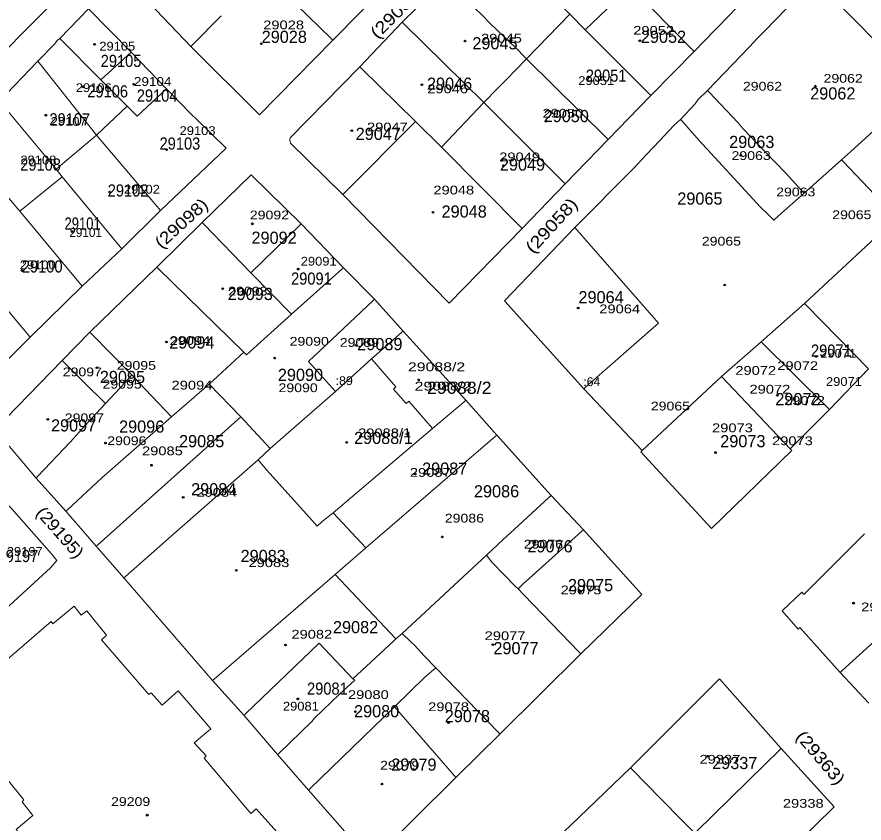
# Model space of a CAD drawing. Extents: x 650553 to 652508, y 239277 to 241647.
# Drawn here: x 650778.4 to 651029.3, y 239869.5 to 240108.2 of the extents above; entities that cross this region are included whole.
import ezdxf

# ---------------------------------------------------------------- set-up
doc = ezdxf.new("R2010")
doc.units = 0
doc.header["$PDMODE"] = 32
doc.header["$PDSIZE"] = 0.5
for name, color, linetype in [('19', 7, 'Continuous'), ('20', 7, 'Continuous'), ('6', 7, 'Continuous')]:
    doc.layers.add(name, color=color, linetype=linetype)
doc.layers.add('3', color=7, linetype='Continuous', lineweight=13)
doc.layers.add('5', color=7, linetype='Continuous', lineweight=13)

msp = doc.modelspace()

# ---------------------------------------------------------------- linework, layer by layer
at = {"layer": '3'}
for p, q in [((651000, 240104.22), (651014.69, 240119.32)), ((650986.44, 239912.2), (651004.77, 239891.58))]:
    msp.add_line(p, q, dxfattribs=at)
for points in [[(650975.44, 240248.44), (650994.17, 240226.84), (650977.88, 240210.19), (650963.32, 240195.05), (650948.63, 240180.21), (650934.05, 240165.2), (650919.2, 240150.25), (650903.76, 240134.01), (650887.65, 240117.31), (650871.97, 240101.3)], [(650930.92, 240145.99), (650924.769, 240139.63), (650918.26, 240132.9), (650905.2, 240119.22), (650892.49, 240106.64), (650880, 240093.44)], [(650766.31, 240143.8), (650775.98, 240134.27), (650792.47, 240117.44), (650792.29, 240115.83), (650763.49, 240086.71), (650744.41, 240067.5), (650736.33, 240059.47), (650735.05, 240058.07), (650734.43, 240057.51), (650722.23, 240045.33)], [(650871.97, 240101.3), (650850.3, 240079.24), (650829.93, 240099.47), (650819.64, 240110.18), (650810.53, 240119.41)], [(650773.2, 240083.22), (650784.6, 240095.08), (650789.44, 240100.03), (650790.43, 240101.3), (650791.13, 240101.84), (650799.66, 240110.57), (650812.24, 240097.72), (650822.72, 240086.91), (650830, 240079.39), (650831.7, 240077.84), (650840.34, 240069.3), (650820.91, 240050.84), (650809.49, 240039.55), (650797.79, 240028.48), (650782.37, 240013.42), (650768.89, 240000)], [(650978.95, 240097.99), (650985.03, 240104.18), (650986.07, 240105.29), (650991.82, 240111.21)], [(651000, 240104.22), (650997.68, 240101.84), (650995.41, 240099.33), (650982.94, 240086.4)], [(650953.53, 240071.89), (650962.616, 240081.263), (650966.16, 240084.92), (650978.95, 240097.99)], [(650880, 240093.44), (650859.32, 240072.42), (650859.21, 240071.78), (650859.48, 240070.81), (650874.97, 240055.59)], [(650982.94, 240086.4), (650980.21, 240083.73), (650979.27, 240082.47), (650974.97, 240077.81)], [(650974.97, 240077.81), (650974.27, 240077.27), (650972.98, 240076), (650968.861, 240071.631), (650964.91, 240067.44), (650960.97, 240063.32), (650943.69, 240045.86)], [(650928.01, 240045.51), (650940.8, 240058.76), (650953.53, 240071.89)], [(650833.3, 240047.34), (650847.81, 240061.43), (650862.6, 240046.9), (650875.1, 240033.95), (650884.29, 240024.61), (650892.8, 240015.16), (650911.36, 239994.7), (650920.54, 239984.38), (650936.59, 239966.5), (650946.16, 239956.31), (650963.51, 239937.15)], [(650874.97, 240055.59), (650906.41, 240023.45), (650928.01, 240045.51)], [(650771.89, 239986.02), (650791.8, 240006.47), (650800.06, 240014.9), (650819.81, 240034.14), (650833.3, 240047.34)], [(650943.69, 240045.86), (650922.798, 240024.153), (650946.26, 239998.12), (650963.63, 239979.83)], [(650963.63, 239979.83), (650963.19, 239979.42), (650984.08, 239956.68), (651007.923, 239979.861), (651007.45, 239980.27), (651019.018, 239991.973), (651030.64, 240004.03)], [(650908.41, 239883.02), (650883.34, 239858.18), (650864.77, 239879.28), (650855.55, 239889.77), (650845.58, 239901.42), (650836.36, 239911.69), (650810.07, 239942.07), (650801.92, 239951.45), (650792.87, 239961.83), (650784.09, 239971.6), (650771.89, 239986.02)], [(650775.13, 239932.91), (650788.329, 239945.049), (650790.275, 239947.215), (650788.627, 239949.191), (650776.82, 239962.65), (650762.84, 239977.13)], [(651029.394, 239955.14), (651011.428, 239937.153), (651010.901, 239937.895), (651005.075, 239932.349), (651009.776, 239926.918), (651010.311, 239927.45), (651022.23, 239914.101), (651030.731, 239905.003)], [(650963.51, 239937.15), (650945.45, 239919.6), (650921.48, 239895.81), (650908.41, 239883.02)], [(650758.53, 239902.67), (650765.192, 239907.872), (650764.516, 239908.49), (650788.613, 239929.179), (650789.086, 239928.488), (650795.35, 239933.7), (650797.42, 239931.11), (650799.14, 239932.39), (650804.99, 239925.16), (650803.46, 239923.73), (650817.53, 239907.6), (650818.21, 239908.05), (650821.441, 239904.446), (650826.146, 239908.699), (650835.897, 239897.399), (650830.96, 239893.24), (650834.46, 239889.42), (650833.85, 239888.76), (650847.66, 239872.31), (650849.29, 239873.74), (650855.37, 239866.92), (650854.34, 239866.07), (650856.61, 239863.11), (650871.916, 239846.694)], [(650926.38, 239808.25), (650907.36, 239830.06), (650907.67, 239834.39), (650925.58, 239852.98), (650942.36, 239868.78), (650960.13, 239885.88), (650986.44, 239912.2)], [(650758.53, 239902.67), (650760.73, 239900.19), (650759.19, 239898.72), (650765.32, 239891.73), (650766.99, 239892.99), (650780.49, 239876.39), (650779.94, 239875.79), (650783.12, 239871.78), (650778.188, 239867.604), (650787.995, 239856.292), (650792.37, 239860.72), (650795.54, 239856.63), (650796.29, 239857.11), (650810.17, 239840.72), (650808.48, 239839.35), (650814.17, 239832.2), (650815.19, 239833.07), (650817.72, 239830.34), (650834.635, 239810.007), (650871.916, 239846.694)], [(651004.77, 239891.58), (651020.46, 239874.33), (651009.06, 239863.21), (651008.47, 239863.96), (650986.02, 239841.96), (650973.43, 239829.74), (650960.91, 239817.58), (650937.89, 239794.94), (650926.38, 239808.25)]]:
    msp.add_lwpolyline(points, dxfattribs=at)
at = {"layer": '5'}
for p, q in [((650929.29, 240095.81), (650942.18, 240109.01)), ((650803.28, 240089.58), (650812.24, 240097.72)), ((650779.32, 240050.7), (650791.83, 240060.84)), ((650943.69, 240045.86), (650968.38, 240017.56)), ((650998.84, 240012), (650987.12, 240001.73)), ((650864.75, 240006.2), (650872.74, 239997.26)), ((650798.34, 240000), (650804.67, 239993.75)), ((650812.46, 240002.19), (650810.44, 240000)), ((650814.53, 240000), (650824.2, 239989.77)), ((650987.12, 240001.73), (650963.63, 239979.83)), ((650987.12, 240001.73), (651007.45, 239980.27)), ((650872.07, 239961.33), (650881.77, 239950.98)), ((650872.65, 239943.08), (650890.65, 239924.09))]:
    msp.add_line(p, q, dxfattribs=at)
for points in [[(650918.26, 240132.9), (650918.76, 240132.401), (650942.18, 240109.01), (650946.68, 240104.38)], [(650854.33, 240118.56), (650871.47, 240101.789), (650871.97, 240101.3)], [(650905.2, 240119.22), (650905.7, 240118.739), (650916.28, 240108.57), (650918.43, 240106.37), (650924.82, 240100.3), (650925.76, 240099.39), (650929.29, 240095.81)], [(651014.69, 240119.32), (651015.181, 240118.82), (651034.33, 240099.34), (651038, 240095.56)], [(650946.68, 240104.38), (650950.89, 240108.34), (650956.05, 240113.4), (650959.96, 240117.36)], [(650959.96, 240117.36), (650978.46, 240098.49), (650978.95, 240097.99)], [(650829.93, 240099.47), (650830.427, 240099.97), (650838.9, 240108.5)], [(650892.49, 240106.64), (650892.99, 240106.148), (650916.68, 240082.82)], [(650946.68, 240104.38), (650965.66, 240085.419), (650966.16, 240084.92)], [(650791.13, 240101.84), (650803.28, 240089.58), (650811.03, 240081.77), (650814, 240078.82), (650822.72, 240086.91)], [(650904.16, 240069.62), (650916.68, 240082.82), (650920.75, 240087.02), (650923.24, 240089.48), (650929.29, 240095.81)], [(650929.29, 240095.81), (650953.03, 240072.383), (650953.53, 240071.89)], [(650784.6, 240095.08), (650801.99, 240073.14), (650820.91, 240050.84)], [(650880, 240093.44), (650880.5, 240092.949), (650896.49, 240077.25), (650904.16, 240069.62), (650928.01, 240045.51)], [(650982.94, 240086.4), (650983.414, 240085.9), (650992.02, 240076.82), (650993.53, 240075.08), (651000, 240068.28)], [(651022.59, 240065.87), (651025.24, 240068.24), (651034.21, 240076.35), (651037.83, 240079.55), (651046.01, 240087.16)], [(650773.2, 240083.22), (650790.02, 240063.09), (650791.83, 240060.84), (650809.49, 240039.55)], [(650916.68, 240082.82), (650940.3, 240059.259), (650940.8, 240058.76)], [(650790.02, 240063.09), (650801.99, 240073.14), (650811.03, 240081.77)], [(650974.97, 240077.81), (650975.415, 240077.31), (650981.3, 240070.69), (650982.86, 240069.06), (650998.65, 240051.9)], [(650874.97, 240055.59), (650875.467, 240056.09), (650896.49, 240077.25)], [(650761.69, 240071.64), (650777.54, 240052.71), (650779.32, 240050.7), (650797.79, 240028.48)], [(651000, 240068.28), (651006.11, 240061.9), (651011.052, 240056.51), (651011.51, 240056.01)], [(650999.859, 240050.655), (651000.5, 240050.041), (651002.6, 240048.03), (651003.92, 240049.33), (651011.51, 240056.01), (651022.59, 240065.87)], [(651022.59, 240065.87), (651023.066, 240065.37), (651038.214, 240049.46), (651038.69, 240048.96)], [(650998.84, 240012), (651011.61, 240023.38), (651031.17, 240041.53), (651038.69, 240048.96), (651043.31, 240052.81), (651055.09, 240063.85)], [(650750.35, 240060.27), (650766.03, 240041.88), (650761.91, 240037.76), (650782.37, 240013.42)], [(650998.65, 240051.9), (650999.514, 240051.01), (650999.859, 240050.655)], [(650833.3, 240047.34), (650833.784, 240046.84), (650847.72, 240032.43), (650859.71, 240020.15)], [(650847.72, 240032.43), (650862.1, 240046.414), (650862.6, 240046.9)], [(650819.81, 240034.14), (650820.31, 240033.651), (650845.59, 240008.91)], [(650875.1, 240033.95), (650874.6, 240033.502), (650859.71, 240020.15), (650846.38, 240008.1), (650845.59, 240008.91), (650835.4, 239999.46)], [(650884.29, 240024.61), (650883.79, 240024.139), (650864.75, 240006.2)], [(651011.61, 240023.38), (651012.102, 240022.88), (651030.64, 240004.03)], [(650968.38, 240017.56), (650946.76, 239998.559), (650946.26, 239998.12)], [(650800.06, 240014.9), (650800.548, 240014.4), (650812.46, 240002.19), (650814.53, 240000)], [(650892.8, 240015.16), (650892.3, 240014.723), (650883.43, 240006.97), (650872.74, 239997.26)], [(650998.84, 240012), (651018.518, 239992.469), (651019.018, 239991.973)], [(650791.8, 240006.47), (650792.3, 240005.975), (650798.34, 240000)], [(650883.43, 240006.97), (650890.671, 239998.708), (650889.908, 239997.999), (650893.73, 239993.745), (650894.519, 239994.454), (650901.48, 239986.3)], [(650810.44, 240000), (650804.67, 239993.75), (650800.53, 239989.25), (650794.31, 239982.43)], [(650835.4, 239999.46), (650824.2, 239989.77), (650803.59, 239971.68)], [(650835.4, 239999.46), (650844.71, 239989.81), (650853.45, 239980.41)], [(650872.74, 239997.26), (650853.45, 239980.41), (650849.87, 239977.03), (650826.58, 239956.58), (650822.45, 239953)], [(650911.36, 239994.7), (650910.86, 239994.275), (650901.48, 239986.3), (650872.07, 239961.33), (650868.82, 239958.76), (650867.29, 239957.46), (650865.02, 239960), (650853.32, 239973.05), (650852.44, 239974), (650849.87, 239977.03)], [(650844.71, 239989.81), (650802.42, 239951.898), (650801.92, 239951.45)], [(650794.31, 239982.43), (650784.562, 239972.1), (650784.09, 239971.6)], [(650920.54, 239984.38), (650920.04, 239983.949), (650881.77, 239950.98), (650872.65, 239943.08)], [(650803.59, 239971.68), (650793.37, 239962.289), (650792.87, 239961.83)], [(650936.59, 239966.5), (650936.09, 239966.04), (650926.92, 239957.6), (650922.32, 239953.37), (650917.47, 239948.86), (650892.47, 239925.68), (650890.65, 239924.09), (650889.94, 239923.37), (650877.89, 239912.21), (650867.89, 239922.79)], [(650946.16, 239956.31), (650945.66, 239955.862), (650928.27, 239940.29), (650926.85, 239938.86)], [(650822.45, 239953), (650810.57, 239942.511), (650810.07, 239942.07)], [(650917.47, 239948.86), (650919.1, 239946.75), (650926.16, 239939.49), (650926.85, 239938.86), (650928.52, 239937.04)], [(650872.65, 239943.08), (650836.86, 239912.122), (650836.36, 239911.69)], [(650928.52, 239937.04), (650944.965, 239920.1), (650945.45, 239919.6)], [(651022.23, 239914.101), (651022.73, 239914.554), (651046.15, 239935.78)], [(650892.47, 239925.68), (650895.08, 239923.13), (650896.15, 239922.14), (650898.98, 239919.06), (650902.44, 239915.48)], [(650867.89, 239922.79), (650846.08, 239901.899), (650845.58, 239901.42)], [(650902.44, 239915.48), (650899.25, 239912.73), (650890.26, 239903.97)], [(650902.44, 239915.48), (650920.996, 239896.31), (650921.48, 239895.81)], [(650877.89, 239912.21), (650878.49, 239911.87), (650873.99, 239907.67), (650866.54, 239900.55), (650865.71, 239899.54)], [(650890.26, 239903.97), (650865.27, 239879.764), (650864.77, 239879.28)], [(650890.26, 239903.97), (650907.977, 239883.52), (650908.41, 239883.02)], [(650865.71, 239899.54), (650856.05, 239890.251), (650855.55, 239889.77)], [(651000, 239886.91), (651004.27, 239891.09), (651004.77, 239891.58)], [(651000, 239886.91), (650979.43, 239866.78), (650979.19, 239866.43), (650977.59, 239864.89), (650976.17, 239863.49), (650970.39, 239857.73), (650961.58, 239849), (650957.95, 239845.67), (650945.33, 239833.29)], [(650960.13, 239885.88), (650960.617, 239885.38), (650968.98, 239876.79), (650975.37, 239870.37), (650978.06, 239867.64), (650979.19, 239866.43)]]:
    msp.add_lwpolyline(points, dxfattribs=at)
at = {"layer": '6'}
for p in [(650801.407, 240100.075), (650850.812, 240100.24), (650911.13, 240101.02), (650962.893, 240101.14), (650947.673, 240090.45), (650797.985, 240087.49), (650812.991, 240088.27), (650898.348, 240088.13), (651014.845, 240087.665), (650786.966, 240079.085), (650935.146, 240077.285), (650877.577, 240074.515), (650822.751, 240068.875), (650992.789, 240067.215), (650922.469, 240064.165), (650805.899, 240056.345), (650901.659, 240050.35), (650848.133, 240046.93), (650794.796, 240044.66), (650779.918, 240033.065), (650861.736, 240033.525), (650839.344, 240027.72), (650988.014, 240028.82), (650944.631, 240021.99), (650822.706, 240011.955), (650878.871, 240010.935), (650854.757, 240007.18), (651015.125, 240007.676), (650802.173, 240004.325), (650897.394, 240000.73), (651003.622, 239996.135), (650787.58, 239989.035), (650876.093, 239982.215), (650804.636, 239982.01), (650985.318, 239979.205), (650818.294, 239975.455), (650896.386, 239972.84), (650827.662, 239965.94), (650904.405, 239954.235), (650931.842, 239952.68), (650843.396, 239944.36), (650945.231, 239937.955), (651026.165, 239934.62), (650857.948, 239922.25), (650919.367, 239922.335), (650861.595, 239906.28), (650878.641, 239902.48), (650906.25, 239899.25), (650983.01, 239889.315), (650886.535, 239881.075), (650817.017, 239871.853)]:
    msp.add_point(p, dxfattribs=at)

# ---------------------------------------------------------------- texts
at = {"layer": '19'}
for s, rotation, width, p in [('(29037)', 44.915, 1.2, (650885.223, 240101.459)), ('(29098)', 42.188, 1.15, (650821.228, 240039.361)), ('(29058)', 47.399, 1.2, (650931.314, 240037.878)), ('(29195)', 311.276, 1.1, (650783.835, 239961.229)), ('(29363)', 310.486, 1.15, (651008.862, 239894.966))]:
    msp.add_text(s, height=3.6, rotation=rotation, dxfattribs=dict(at, width=width)).set_placement(p)
for s, p in [('29028', (650850.909, 240100.506)), ('29052', (650963.201, 240100.506)), ('29045', (650913.293, 240098.59)), ('29046', (650899.858, 240086.619)), ('29062', (651013.339, 240083.744)), ('29050', (650934.408, 240077.041)), ('29047', (650878.743, 240071.774)), ('29063', (650989.346, 240069.378)), ('29049', (650921.452, 240062.676)), ('29065', (650973.99, 240052.618)), ('29048', (650904.176, 240048.789)), ('29092', (650847.888, 240041.017)), ('29093', (650840.825, 240024.366)), ('29064', (650944.716, 240023.407)), ('29094', (650823.548, 240010)), ('29089', (650879.214, 240009.521)), ('29095', (650802.981, 239999.789)), ('29090', (650855.7, 240000.423)), ('29072', (651003.021, 239993.24)), ('29097', (650788.518, 239985.456)), ('29096', (650808.673, 239985.1)), ('29088/1', (650878.254, 239981.747)), ('29085', (650826.429, 239980.79)), ('29073', (650986.705, 239980.789)), ('29087', (650898.411, 239972.649)), ('29084', (650830.017, 239966.546)), ('29086', (650913.767, 239965.945)), ('29076', (650929.601, 239949.664)), ('29083', (650844.664, 239946.79)), ('29075', (650941.598, 239938.171)), ('29082', (650872.017, 239925.721)), ('29077', (650919.524, 239919.495)), ('29080', (650878.254, 239900.82)), ('29078', (650905.128, 239899.383)), ('29079', (650889.292, 239885.018)), ('29337', (650984.308, 239885.496))]:
    msp.add_text(s, height=3.6, dxfattribs=at).set_placement(p)
for s, width, p in [('29105', 0.9, (650803.235, 240093.382)), ('29051', 0.9, (650946.885, 240089.013)), ('29106', 0.9, (650799.279, 240084.346)), ('29104', 0.9, (650813.927, 240083.11)), ('29107', 0.9, (650788.04, 240076.083)), ('29103', 0.9, (650820.67, 240068.9)), ('29108', 0.9, (650779.401, 240062.675)), ('29102', 0.9, (650805.314, 240055.013)), ('29101', 0.8, (650792.518, 240045.226)), ('29100', 0.9, (650779.88, 240032.507)), ('29091', 0.9, (650859.606, 240028.922)), ('29071', 0.9, (651013.578, 240007.605)), ('29088/2', 1.1, (650899.848, 239996.592)), ('29197', 0.9, (650772.689, 239946.79)), ('29081', 0.9, (650864.339, 239907.524))]:
    msp.add_text(s, height=3.6, dxfattribs=dict(at, width=width)).set_placement(p)
at = {"layer": '20'}
for s, width, p in [('29028', 1.25, (650851.359, 240104.523)), ('29052', 1.25, (650960.941, 240102.909)), ('29045', 1.25, (650915.872, 240100.591)), ('29105', 1.1, (650802.823, 240098.231)), ('29104', 1.15, (650813.073, 240087.775)), ('29051', 1.1, (650944.65, 240088.033)), ('29062', 1.2, (651017.302, 240088.698)), ('29106', 1.1, (650795.859, 240085.942)), ('29046', 1.25, (650899.943, 240085.606)), ('29062', 1.2, (650993.415, 240086.361)), ('29050', 1.25, (650934.056, 240078.368)), ('29107', 1.1, (650788.44, 240075.954)), ('29103', 1.1, (650826.594, 240073.222)), ('29047', 1.25, (650882.094, 240074.287)), ('29049', 1.25, (650921.252, 240065.448)), ('29063', 1.2, (650990.053, 240065.828)), ('29108', 1.1, (650779.451, 240064.527)), ('29102', 1.1, (650810.125, 240055.866)), ('29048', 1.25, (650901.748, 240055.638)), ('29063', 1.2, (651003.272, 240055.061)), ('29092', 1.2, (650847.403, 240048.246)), ('29065', 1.2, (651019.868, 240048.317)), ('29065', 1.2, (650981.259, 240040.495)), ('29100', 1.1, (650779.267, 240033.497)), ('29091', 1.1, (650862.473, 240034.556)), ('29093', 1.2, (650841.028, 240025.716)), ('29064', 1.25, (650950.883, 240020.445)), ('29094', 1.25, (650823.626, 240011.055)), ('29090', 1.2, (650859.185, 240010.84)), ('29089', 1.2, (650874.046, 240010.516)), ('29071', 1.1, (651016.318, 240007.29)), ('29095', 1.2, (650807.988, 240003.725)), ('29088/2', 1.35, (650894.21, 240003.295)), ('29072', 1.25, (650991.169, 240002.226)), ('29072', 1.25, (651003.596, 240003.635)), ('29097', 1.2, (650791.99, 240001.785)), ('29095', 1.2, (650803.777, 239998.158)), ('29094', 1.25, (650824.218, 239997.868)), (':89', 1.05, (650872.814, 239999.184)), ('29088/2', 1.35, (650896.208, 239997.583)), (':64', 1.05, (650946.126, 239998.886)), ('29071', 1.1, (651018.012, 239998.937)), ('29090', 1.2, (650855.899, 239997.094)), ('29072', 1.25, (650995.357, 239996.656)), ('29072', 1.25, (651005.616, 239993.319)), ('29065', 1.2, (650966.149, 239991.681)), ('29097', 1.2, (650792.604, 239988.189)), ('29073', 1.25, (650984.281, 239985.232)), ('29088/1', 1.25, (650879.461, 239983.742)), ('29096', 1.2, (650805.173, 239981.413)), ('29073', 1.25, (651002.035, 239981.399)), ('29085', 1.25, (650815.469, 239978.416)), ('29087', 1.25, (650894.795, 239972.03)), ('29084', 1.25, (650831.594, 239966.123)), ('29086', 1.2, (650905.138, 239958.479)), ('29076', 1.2, (650928.539, 239950.778)), ('29197', 1.1, (650775.43, 239948.646)), ('29083', 1.25, (650847.011, 239945.301)), ('29075', 1.25, (650939.438, 239937.227)), ('29378', 1.25, (651028.424, 239932.206)), ('29082', 1.25, (650859.711, 239924.103)), ('29077', 1.25, (650916.938, 239923.676)), ('29080', 1.25, (650876.453, 239906.234)), ('29081', 1.1, (650857.197, 239902.809)), ('29078', 1.25, (650900.213, 239902.653)), ('29337', 1.25, (650980.561, 239887.095)), ('29079', 1.2, (650885.981, 239885.327)), ('29209', 1.2, (650806.297, 239874.564)), ('29338', 1.25, (651005.249, 239874.041))]:
    msp.add_text(s, height=2.6, dxfattribs=dict(at, width=width)).set_placement(p)
msp.add_text('29101', height=2.6, dxfattribs=at).set_placement((650793.941, 240043.038))

doc.saveas('drawing.dxf')
